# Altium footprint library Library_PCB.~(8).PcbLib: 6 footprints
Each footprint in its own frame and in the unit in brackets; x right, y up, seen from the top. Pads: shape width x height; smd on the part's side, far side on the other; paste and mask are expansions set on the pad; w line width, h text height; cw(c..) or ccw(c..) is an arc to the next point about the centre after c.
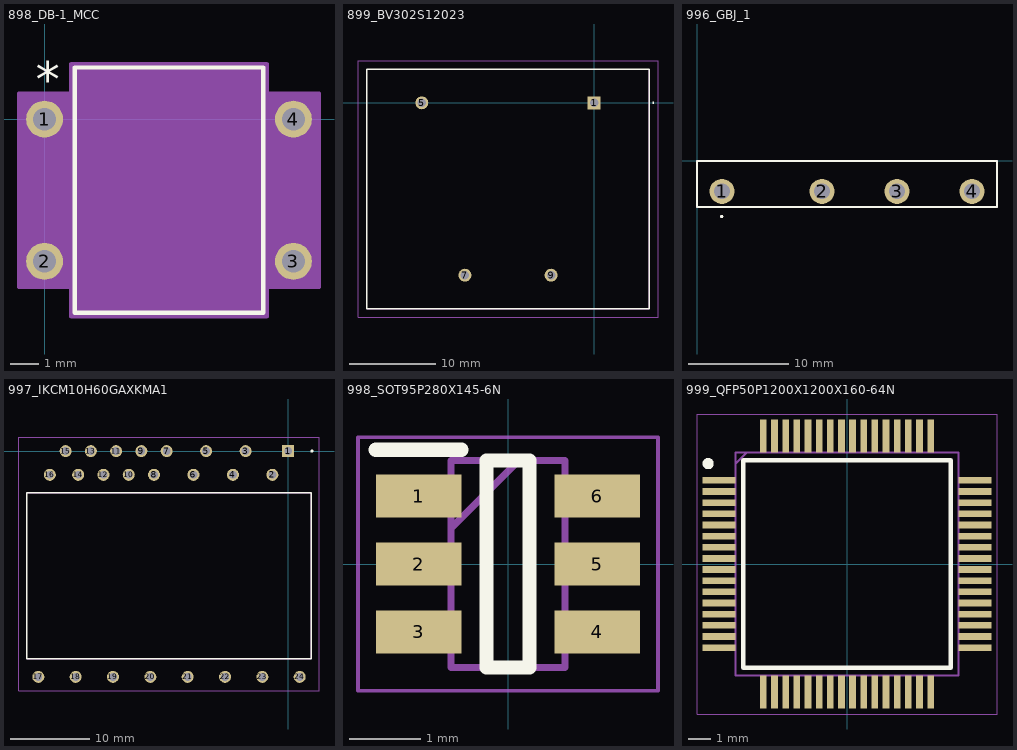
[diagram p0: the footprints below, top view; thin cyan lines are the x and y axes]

## 898_DB-1_MCC [mil]
pads (4):
  round 52 hole 32 paste-99999 mask+0: 1(0,0) 2(0,-200) 3(350,-200) 4(350,0)
Top Overlay:
  lines w6: 42.5,-272.5 307.5,-272.5 307.5,72.5 42.5,72.5 42.5,-272.5
  text "*" at -12.5,31 h50
  text ".Designator" at 37.5,-125 h50
Mechanical 13:
  lines w1: 163,67.5 ccw(c175,67.5) 187,67.5 ; -16,-216 -16,-184 47.5,-184 47.5,-216 -16,-216 ; -16,-16 -16,16 47.5,16 47.5,-16 -16,-16 ; 47.5,-267.5 302.5,-267.5 302.5,67.5 47.5,67.5 47.5,-267.5 ; 302.5,-216 302.5,-184 366,-184 366,-216 302.5,-216 ; 302.5,-16 302.5,16 366,16 366,-16 302.5,-16
  text ".Designator" at 37.5,-125 h50
  text "*" at 45,-25 h50
Mechanical 15:
  region: 312.5,-236 386,-236 386,36 312.5,36 312.5,77.5 37.5,77.5 37.5,36 -36,36 -36,-236 37.5,-236 37.5,-277.5 312.5,-277.5
  lines w6: -36,-236 -36,36 37.5,36 37.5,77.5 312.5,77.5 312.5,36 386,36 386,-236 312.5,-236 312.5,-277.5 37.5,-277.5 37.5,-236 -36,-236
3D body "DB-1_MCC.step": height 195.12, standoff -100, extent -10,-269.96 360,65

## 899_BV302S12023 [mm]
pads (4):
  rect 1.5x1.5 hole 1: 1(0,0)
  round 1.5 hole 1: 5(-20,0) 7(-15,-20) 9(-5,-20)
Top Overlay:
  lines w0.1: 6.8,0 ccw(c6.85,0) 6.9,0 ccw(c6.85,0) 6.8,0
  lines w0.2: -26.4,-23.9 6.4,-23.9 6.4,3.9 -26.4,3.9 -26.4,-23.9
Mechanical 15:
  lines w0.1: -26.4,-23.9 6.4,-23.9 6.4,3.9 -26.4,3.9 -26.4,-23.9
Mechanical 20:
  lines w0.1: -27.4,-24.9 7.4,-24.9 7.4,4.9 -27.4,4.9 -27.4,-24.9
3D body "BV302S12023.stp": height 29.79, standoff -4, extent -26.429,-23.876 6.362,3.912

## 996_GBJ_1 [mm]
pads (4):
  round 2.5 hole 1.56: 1(2.5,-3.05) 2(12.5,-3.05) 3(20,-3.05) 4(27.5,-3.05)
Top Overlay:
  circle w0.2: c2.467,-5.567 r0.061
  lines w0.2: 0,-4.6 30,-4.6 30,0 0,0 0,-4.6
Mechanical 13:
  lines w0.2: 0,-4.6 0,0 30,0 30,-4.6 0,-4.6
3D body "GBJ2506-F.stp": height 25.23, standoff -13.07, extent -0.44,-4.69 29.86,0.11

## 997_IKCM10H60GAXKMA1 [mm]
pads (24):
  rect 1.524x1.524 hole 0.98: 1(0,0)
  round 1.524 hole 0.98: 2(-2,-3) 3(-5.4,0) 4(-7,-3) 5(-10.4,0) 6(-12,-3) 7(-15.4,0) 8(-17,-3) 9(-18.6,0) 10(-20.2,-3) 11(-21.8,0) 12(-23.4,-3) 13(-25,0) 14(-26.6,-3) 15(-28.2,0) 16(-30.2,-3) 17(-31.655,-28.6) 18(-26.925,-28.6) 19(-22.195,-28.6) 20(-17.465,-28.6) 21(-12.735,-28.6) 22(-8.005,-28.6) 23(-3.275,-28.6) 24(1.455,-28.6)
Top Overlay:
  lines w0.2: 2.9,0 ccw(c3,0) 3.1,0 ; 2.9,0 cw(c3,0) 3.1,0 ; 2.9,0 ccw(c3,0) 3.1,0 ; -33.1,-26.3 -33.1,-5.3 2.9,-5.3 2.9,-26.3 -33.1,-26.3
Mechanical 15:
  lines w0.1: -33.1,-26.3 -33.1,-5.3 2.9,-5.3 2.9,-26.3 -33.1,-26.3
Mechanical 20:
  lines w0.1: -34.1,-30.362 -34.1,1.762 3.9,1.762 3.9,-30.362 -34.1,-30.362
3D body "IKCM10H60GAXKMA1.stp": height 5.7, standoff -5, extent -33.079,-28.956 2.921,0.418

## 998_SOT95P280X145-6N [mm]
pads (6):
  rect 1.2x0.6 smd: 1(-1.25,0.95) 2(-1.25,0) 3(-1.25,-0.95) 4(1.25,-0.95) 5(1.25,0) 6(1.25,0.95)
Top Overlay:
  lines w0.2: -1.85,1.6 -0.65,1.6 ; -0.3,-1.45 0.3,-1.45 0.3,1.45 -0.3,1.45 -0.3,-1.45
Mechanical 15:
  lines w0.1: -0.8,0.5 0.15,1.45 ; -0.8,-1.45 0.8,-1.45 0.8,1.45 -0.8,1.45 -0.8,-1.45
Mechanical 20:
  lines w0.05: -2.1,-1.775 2.1,-1.775 2.1,1.775 -2.1,1.775 -2.1,-1.775
3D body "TPS560430X3FDBVR.stp": height 1.45, standoff 0, extent -1.4,-1.45 1.4,1.45

## 999_QFP50P1200X1200X160-64N [mm]
pads (64):
  rect 1.475x0.3 smd: 1(-5.738,3.75) 2(-5.738,3.25) 3(-5.738,2.75) 4(-5.738,2.25) 5(-5.738,1.75) 6(-5.738,1.25) 7(-5.738,0.75) 8(-5.738,0.25) 9(-5.738,-0.25) 10(-5.738,-0.75) 11(-5.738,-1.25) 12(-5.738,-1.75) 13(-5.738,-2.25) 14(-5.738,-2.75) 15(-5.738,-3.25) 16(-5.738,-3.75) 33(5.738,-3.75) 34(5.738,-3.25) 35(5.738,-2.75) 36(5.738,-2.25) 37(5.738,-1.75) 38(5.738,-1.25) 39(5.738,-0.75) 40(5.738,-0.25) 41(5.738,0.25) 42(5.738,0.75) 43(5.738,1.25) 44(5.738,1.75) 45(5.738,2.25) 46(5.738,2.75) 47(5.738,3.25) 48(5.738,3.75)
  rect 0.3x1.475 smd: 17(-3.75,-5.738) 18(-3.25,-5.738) 19(-2.75,-5.738) 20(-2.25,-5.738) 21(-1.75,-5.738) 22(-1.25,-5.738) 23(-0.75,-5.738) 24(-0.25,-5.738) 25(0.25,-5.738) 26(0.75,-5.738) 27(1.25,-5.738) 28(1.75,-5.738) 29(2.25,-5.738) 30(2.75,-5.738) 31(3.25,-5.738) 32(3.75,-5.738) 49(3.75,5.738) 50(3.25,5.738) 51(2.75,5.738) 52(2.25,5.738) 53(1.75,5.738) 54(1.25,5.738) 55(0.75,5.738) 56(0.25,5.738) 57(-0.25,5.738) 58(-0.75,5.738) 59(-1.25,5.738) 60(-1.75,5.738) 61(-2.25,5.738) 62(-2.75,5.738) 63(-3.25,5.738) 64(-3.75,5.738)
Top Overlay:
  circle w0.25: c-6.225,4.5 r0.125
  lines w0.2: -4.65,-4.65 -4.65,4.65 4.65,4.65 4.65,-4.65 -4.65,-4.65
Mechanical 15:
  lines w0.1: -5,4.5 -4.5,5 ; -5,-5 -5,5 5,5 5,-5 -5,-5
Mechanical 20:
  lines w0.05: -6.725,-6.725 -6.725,6.725 6.725,6.725 6.725,-6.725 -6.725,-6.725
3D body "STM32G431RBT6.stp": height 1.6, standoff 0, extent -6,-6 6,6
